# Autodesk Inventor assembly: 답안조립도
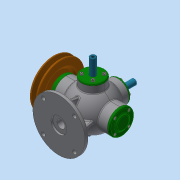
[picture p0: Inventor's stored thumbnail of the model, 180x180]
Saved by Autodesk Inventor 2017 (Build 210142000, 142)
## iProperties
Part Number: 답안조립도
Material: 일반
Document SubType Name: Assembly
Designer: MRC
Mass: 2806.2 g
Surface Area: 2410.88 cm^2
Volume: 904.614 cm^3
Density: 3.1021 g/cm^3
Author: MRC
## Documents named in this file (17)
- C:\Users\MRC\Desktop\600911V1008\답안조립도.iam
- C:\Users\MRC\Desktop\600911V1008\본체.ipt
- C:\Users\MRC\Desktop\600911V1008\Ű 4x4.ipt
- C:\Users\MRC\Desktop\600911V1008\V-벨트풀리.ipt
- C:\Users\MRC\Desktop\600911V1008\너트 M8x1.ipt
- C:\Users\MRC\Desktop\600911V1008\뒤커버.ipt
- C:\Users\MRC\Desktop\600911V1008\베어링 6202.ipt
- C:\Users\MRC\Desktop\600911V1008\본체커버.ipt
- C:\Users\MRC\Desktop\600911V1008\볼트 M4.ipt
- C:\Users\MRC\Desktop\600911V1008\스프링1.ipt
- C:\Users\MRC\Desktop\600911V1008\스프링2.ipt
- C:\Users\MRC\Desktop\600911V1008\슬라이드 커버.ipt
- C:\Users\MRC\Desktop\600911V1008\슬라이드.ipt
- C:\Users\MRC\Desktop\600911V1008\앞커버.ipt
- C:\Users\MRC\Desktop\600911V1008\오일 실.ipt
- C:\Users\MRC\Desktop\600911V1008\와셔 8x17.ipt
- C:\Users\MRC\Desktop\600911V1008\축.ipt
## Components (1 placed, 1 different names)
1. V-벨트풀리:1
